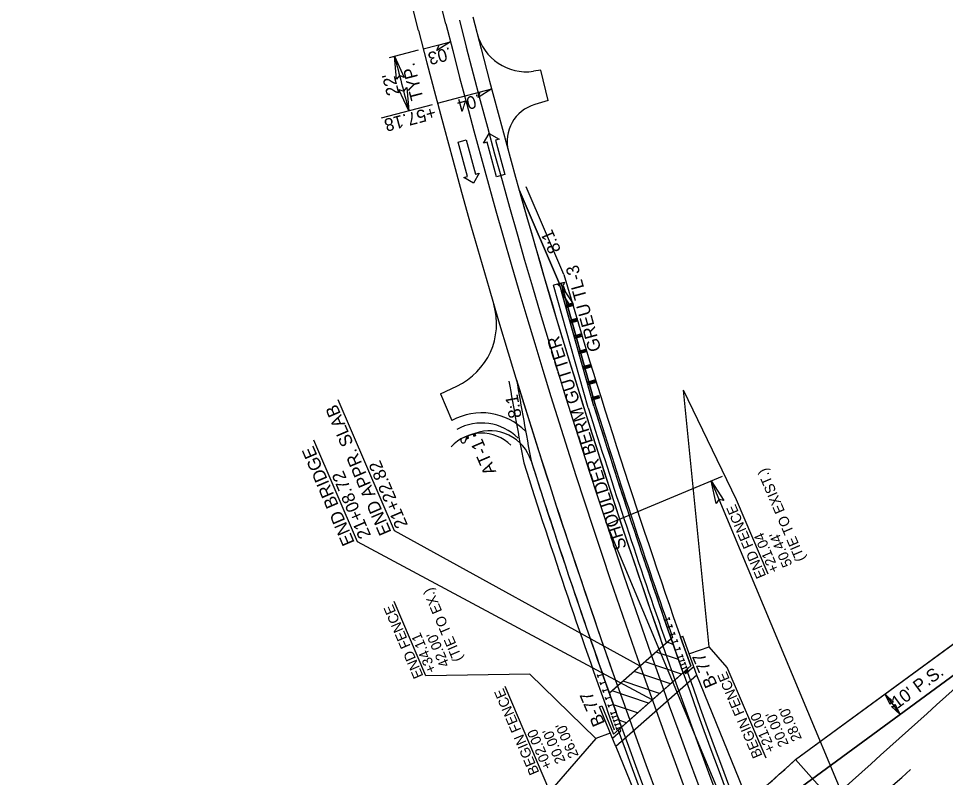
# Model space of a CAD drawing. Extents: x 1550950 to 1552827, y 809595 to 812050.
# Drawn here: x 1551529.1 to 1551892.9, y 810831.5 to 811129.6 of the extents above; entities that cross this region are included whole.
import ezdxf

# ---------------------------------------------------------------- set-up
doc = ezdxf.new("R2010")
doc.units = 0
for name, color, linetype in [('3D Cell Connection Region', 7, 'Continuous'), ('_CIVIL_CONSTRUCTION', 7, 'Continuous'), ('Catch Basin Box 24 Dia-Bottom CELL', 7, 'Continuous'), ('Construction Elements LEVEL', 7, 'Continuous'), ('Draft_Plan_Labels', 7, 'Continuous'), ('Drop Inlet Box Traffic Bearing 840 35-Bottom CELL', 7, 'Continuous'), ('Drop Inlet Box Type B 36 Dia-Bottom CELL', 7, 'Continuous'), ('Drop Inlet Grate 2 Narrow Slot and Flat Grates 840 29 36 Dia BD Apron-Top CELL', 7, 'Continuous'), ('Drop Inlet Grate 2 Narrow Slot and Flat Grates 840 29 36 Dia BD CELL', 7, 'Continuous'), ('Drop Inlet Grate 2 Narrow Slot and Flat Grates 840 29 36 Dia TB-Top CELL', 7, 'Continuous'), ('Drop Inlet Grate 2 Wide Slot and Flat Grates 840 20 36 Dia BD-Top CELL', 7, 'Continuous'), ('Drop Inlet Grate 3 Narrow Slot and Flat Grates 840 29 48 Dia-Top CELL', 7, 'Continuous'), ('Drop Inlet Grate 840 16 CELL', 7, 'Continuous'), ('E_NCDOT_Vertical_Profile_Ground_Line', 7, 'Continuous'), ('Junction Box with Slab Lid 840 31 66 Dia TB CELL', 7, 'Continuous'), ('P_HYD_Ditch_Flow_Arrow', 7, 'Continuous'), ('P_HYD_Drop_Inlet_Box_Traffic_Bearing_840_35-Bottom_CELL', 7, 'Continuous'), ('P_HYD_Pipe_RCP_15in_Class_III', 7, 'Continuous'), ('P_HYD_Pipe_RCP_Class_III', 7, 'Continuous'), ('P_NCDOT_SS_Cut_Line', 7, 'Continuous'), ('P_NCDOT_SS_Transition_Line', 7, 'Continuous'), ('RipRap Pad at Outlet CELL', 7, 'Continuous'), ('Typical Terminator CELL', 7, 'Continuous'), ('V Ditch Special Lateral Detail CELL', 7, 'Continuous'), ('V Ditch Special Lateral with PSRM Detail CELL', 7, 'Continuous')]:
    doc.layers.add(name, color=color, linetype=linetype)

msp = doc.modelspace()

# ---------------------------------------------------------------- linework, layer by layer
at = {"layer": '3D Cell Connection Region'}
for p, q in [((1551687.97, 811117.71), (1551698.63, 811120.44)), ((1551693.54, 811096.34), (1551714.81, 811101.97))]:
    msp.add_line(p, q, dxfattribs=at)
at = {"layer": '_CIVIL_CONSTRUCTION'}
for p, q in [((1551674.76, 811114.32), (1551686.03, 811117.22)), ((1551671.61, 811090.54), (1551691.61, 811095.83)), ((1551869.2, 810864.26), (1551875.12, 810856.2))]:
    msp.add_line(p, q, dxfattribs=at)
msp.add_arc((1554524.17, 811845.14), 2939.64, 194.38517, 194.81729, dxfattribs=at)
at = {"layer": 'Construction Elements LEVEL'}
for centre, radius, start, end in [((1554524.17, 811845.14), 2902, 197.40029, 199.12785), ((1551714.11, 810950.64), 17, 17.6574, 110.1482), ((1554524.17, 811845.14), 2932, 197.65742, 199.36731)]:
    msp.add_arc(centre, radius, start, end, dxfattribs=at)
at = {"layer": 'Draft_Plan_Labels'}
for points in [[(1551823.4, 810911.35), (1551810.91, 810940.51), (1551790.16, 810983.57)], [(1551773.14, 810875.24), (1551676.64, 810928.33), (1551654.58, 810979.87)], [(1551777.86, 810861.95), (1551662.11, 810924.02), (1551645.02, 810963.96)], [(1551729.74, 810872.08), (1551689.01, 810871.43), (1551676.53, 810900.59)], [(1551822.53, 810839.05), (1551807.3, 810874.62), (1551800.15, 810882.85)], [(1551755.67, 810846.81), (1551737.69, 810825.98), (1551720.06, 810867.17)]]:
    msp.add_lwpolyline(points, dxfattribs=at)
at = {"layer": 'Drop Inlet Box Traffic Bearing 840 35-Bottom CELL'}
for p, q in [((1551788.97, 810886.59), (1551789.91, 810886.93)), ((1551792.96, 810875.28), (1551788.97, 810886.59)), ((1551795.29, 810871.67), (1551789.91, 810886.93)), ((1551792.96, 810875.28), (1551762.64, 810848.53)), ((1551794.13, 810874.97), (1551790.94, 810872.16)), ((1551795.29, 810871.67), (1551763.55, 810843.66)), ((1551790.94, 810872.16), (1551790.58, 810873.18)), ((1551815.6, 810821.96), (1551795.29, 810871.67)), ((1551757.18, 810859.25), (1551758.11, 810859.63)), ((1551763.55, 810843.66), (1551757.18, 810859.25)), ((1551758.11, 810859.63), (1551762.64, 810848.53)), ((1551765.52, 810849.73), (1551762.25, 810846.84)), ((1551765.52, 810849.73), (1551765.15, 810850.74)), ((1551763.55, 810843.66), (1551783.9, 810793.84))]:
    msp.add_line(p, q, dxfattribs=at)
at = {"layer": 'Drop Inlet Box Type B 36 Dia-Bottom CELL'}
for p, q in [((1551741.39, 811025.43), (1551725.6, 811062.32)), ((1551834.13, 810838.5), (1551926.9, 810906.66))]:
    msp.add_line(p, q, dxfattribs=at)
for centre, radius, start, end in [((1554591.13, 811489.54), 2910.19, 189.93054, 190.56824), ((1554524.17, 811845.14), 2932, 197.65742, 199.53901), ((1544245.73, 819324.67), 11384.16, 311.678302, 311.803311)]:
    msp.add_arc(centre, radius, start, end, dxfattribs=at)
at = {"layer": 'Drop Inlet Grate 2 Narrow Slot and Flat Grates 840 29 36 Dia BD Apron-Top CELL'}
for radius, end in [(20, 119.2133), (16, 138.5611)]:
    msp.add_arc((1551710.94, 810950.7), radius, 44.6722, end, dxfattribs=at)
at = {"layer": 'Drop Inlet Grate 2 Narrow Slot and Flat Grates 840 29 36 Dia BD CELL'}
for p, q in [((1551759.95, 810930.85), (1551805.44, 810949.86)), ((1551800.94, 810947.98), (1551972.39, 810537.74)), ((1551759.95, 810930.85), (1551931.4, 810520.61))]:
    msp.add_line(p, q, dxfattribs=at)
msp.add_lwpolyline([(1551802.98, 810939.08), (1551800.94, 810947.98), (1551805.9, 810940.25), (1551803.98, 810940.69)], close=True, dxfattribs=at)
msp.add_arc((1554524.17, 811845.14), 2911.5, 194.24112, 221.47505, dxfattribs=at)
at = {"layer": 'Drop Inlet Grate 2 Narrow Slot and Flat Grates 840 29 36 Dia TB-Top CELL'}
for points in [[(1551677.44, 811105.72), (1551676.7, 811114.82), (1551680.5, 811106.45), (1551678.66, 811107.17)], [(1551681.49, 811102.46), (1551682.29, 811093.37), (1551678.43, 811101.71), (1551680.27, 811101)], [(1551871.24, 810860.18), (1551869.2, 810864.26), (1551872.52, 810861.09), (1551871.54, 810861.08)], [(1551873.08, 810860.29), (1551875.12, 810856.2), (1551871.79, 810859.38), (1551872.78, 810859.39)]]:
    msp.add_lwpolyline(points, close=True, dxfattribs=at)
at = {"layer": 'Drop Inlet Grate 2 Wide Slot and Flat Grates 840 20 36 Dia BD-Top CELL'}
for points in [[(1551792.6, 810880.18), (1551800.15, 810882.85), (1551790.16, 810983.57)], [(1551761.32, 810848.84), (1551755.67, 810846.81), (1551729.74, 810872.08)]]:
    msp.add_lwpolyline(points, dxfattribs=at)
at = {"layer": 'Drop Inlet Grate 3 Narrow Slot and Flat Grates 840 29 48 Dia-Top CELL'}
for p, q in [((1551928.66, 810895.54), (1551831.98, 810824.51)), ((1551785.82, 810886.42), (1551782.04, 810883.09)), ((1551764.25, 810867.39), (1551761.01, 810864.54))]:
    msp.add_line(p, q, dxfattribs=at)
for points in [[(1551725.6, 811062.32), (1551741.39, 811025.43), (1551742.03, 811025.61), (1551755.61, 810977.5)], [(1551834.13, 810838.5), (1551926.9, 810906.66), (1551933.24, 810899.72)]]:
    msp.add_lwpolyline(points, dxfattribs=at)
for centre, radius, start, end in [((1554538.86, 811849.77), 2921.39, 195.6373, 199.32316), ((1554591.13, 811489.54), 2910.19, 189.93054, 190.56824), ((1554546.06, 811852.37), 2951.05, 197.03857, 199.49788), ((1554552.91, 811854.67), 2931.6, 197.41026, 199.28573), ((1554553.02, 811854.85), 2962.43, 197.66709, 199.52935), ((1544245.73, 819324.67), 11384.16, 311.340061, 311.803311)]:
    msp.add_arc(centre, radius, start, end, dxfattribs=at)
at = {"layer": 'Drop Inlet Grate 840 16 CELL'}
for points in [[(1551698.63, 811120.44), (1551693.31, 811117.02), (1551694.15, 811119.3)], [(1551714.81, 811101.97), (1551709.52, 811098.5), (1551710.34, 811100.79)]]:
    msp.add_lwpolyline(points, close=True, dxfattribs=at)
at = {"layer": 'E_NCDOT_Vertical_Profile_Ground_Line'}
for p, q in [((1551740.58, 811025.19), (1551743.39, 811026.04)), ((1551741.74, 811024.32), (1551740.58, 811025.19)), ((1551742.34, 811022.36), (1551741.74, 811024.32)), ((1551742.14, 811022.79), (1551743.58, 811023.19)), ((1551743.58, 811023.19), (1551742.41, 811021.82)), ((1551743.39, 811026.04), (1551742.91, 811024.67)), ((1551742.91, 811024.67), (1551743.51, 811022.71)), ((1551743.85, 811022.23), (1551743.58, 811023.19)), ((1551742.14, 811022.79), (1551743.85, 811022.23)), ((1551754.97, 810977.31), (1551742.27, 811022.31)), ((1551742.92, 811022.53), (1551742.34, 811022.36)), ((1551742.41, 811021.82), (1551743.85, 811022.23)), ((1551745.21, 811017.52), (1551742.41, 811021.82)), ((1551743.51, 811022.71), (1551742.92, 811022.53)), ((1551743.85, 811022.23), (1551743.72, 811022.71)), ((1551746.69, 811017.94), (1551743.85, 811022.23)), ((1551743.74, 811017.11), (1551746.69, 811017.94)), ((1551745.48, 811016.56), (1551743.74, 811017.11)), ((1551744.01, 811016.14), (1551745.21, 811017.52)), ((1551744.01, 811016.14), (1551746.96, 811016.98)), ((1551745.48, 811016.56), (1551745.21, 811017.52)), ((1551745.21, 811017.52), (1551746.96, 811016.98)), ((1551746.69, 811017.94), (1551745.48, 811016.56)), ((1551746.96, 811016.98), (1551746.69, 811017.94)), ((1551745.45, 811011.04), (1551748.34, 811011.86)), ((1551747.17, 811010.49), (1551745.45, 811011.04)), ((1551745.72, 811010.08), (1551746.89, 811011.45)), ((1551745.72, 811010.08), (1551748.61, 811010.9)), ((1551747.17, 811010.49), (1551746.89, 811011.45)), ((1551746.89, 811011.45), (1551748.61, 811010.9)), ((1551748.34, 811011.86), (1551747.17, 811010.49)), ((1551748.61, 811010.9), (1551748.34, 811011.86)), ((1551747.16, 811004.98), (1551750.18, 811005.83)), ((1551748.94, 811004.44), (1551747.16, 811004.98)), ((1551747.43, 811004.02), (1551748.67, 811005.4)), ((1551747.43, 811004.02), (1551750.45, 811004.87)), ((1551748.94, 811004.44), (1551748.67, 811005.4)), ((1551748.67, 811005.4), (1551750.45, 811004.87)), ((1551750.18, 811005.83), (1551748.94, 811004.44)), ((1551750.45, 811004.87), (1551750.18, 811005.83)), ((1551748.87, 810998.91), (1551751.8, 810999.74)), ((1551749.15, 810997.95), (1551748.87, 810998.91)), ((1551750.61, 810998.36), (1551748.87, 810998.91)), ((1551749.15, 810997.95), (1551750.33, 810999.33)), ((1551749.15, 810997.95), (1551752.07, 810998.78)), ((1551750.61, 810998.36), (1551750.33, 810999.33)), ((1551750.33, 810999.33), (1551752.07, 810998.78)), ((1551751.8, 810999.74), (1551750.61, 810998.36)), ((1551752.07, 810998.78), (1551751.8, 810999.74)), ((1551750.59, 810992.85), (1551753.52, 810993.68)), ((1551752.32, 810992.3), (1551750.59, 810992.85)), ((1551750.86, 810991.89), (1551752.05, 810993.26)), ((1551750.86, 810991.89), (1551753.79, 810992.72)), ((1551752.32, 810992.3), (1551752.05, 810993.26)), ((1551752.05, 810993.26), (1551753.79, 810992.72)), ((1551753.52, 810993.68), (1551752.32, 810992.3)), ((1551753.79, 810992.72), (1551753.52, 810993.68)), ((1551752.3, 810986.79), (1551755.23, 810987.61)), ((1551754.04, 810986.24), (1551752.3, 810986.79)), ((1551752.57, 810985.82), (1551753.77, 810987.2)), ((1551752.57, 810985.82), (1551755.51, 810986.65)), ((1551754.04, 810986.24), (1551753.77, 810987.2)), ((1551753.77, 810987.2), (1551755.51, 810986.65)), ((1551755.23, 810987.61), (1551754.04, 810986.24)), ((1551755.51, 810986.65), (1551755.23, 810987.61)), ((1551754.01, 810980.72), (1551756.89, 810981.54)), ((1551754.01, 810980.72), (1551755.45, 810981.13)), ((1551754.28, 810979.76), (1551754.01, 810980.72)), ((1551755.72, 810980.17), (1551754.01, 810980.72)), ((1551755.45, 810981.13), (1551754.28, 810979.76)), ((1551754.28, 810979.76), (1551757.17, 810980.57)), ((1551755.72, 810980.17), (1551755.45, 810981.13)), ((1551755.45, 810981.13), (1551757.17, 810980.57)), ((1551756.89, 810981.54), (1551755.72, 810980.17)), ((1551757.17, 810980.57), (1551756.89, 810981.54)), ((1551704.92, 810965.38), (1551703.31, 810964.78)), ((1551704.6, 810963.57), (1551704.95, 810964.73)), ((1551705.39, 810965.55), (1551704.74, 810965.31)), ((1551704.74, 810965.31), (1551704.86, 810964.98)), ((1551704.74, 810965.31), (1551704.86, 810964.98)), ((1551704.74, 810965.31), (1551705.02, 810964.55)), ((1551704.74, 810965.31), (1551705.67, 810964.79)), ((1551704.86, 810965.35), (1551704.99, 810965.4)), ((1551704.86, 810965.35), (1551704.99, 810965.4)), ((1551708.25, 810966.6), (1551704.92, 810965.38)), ((1551705.39, 810965.55), (1551705.02, 810964.55)), ((1551705.02, 810964.55), (1551705.67, 810964.79)), ((1551705.67, 810964.79), (1551705.39, 810965.55)), ((1551708.25, 810966.6), (1551707.59, 810966.36)), ((1551707.59, 810966.36), (1551707.87, 810965.6)), ((1551707.59, 810966.36), (1551708.53, 810965.84)), ((1551708.25, 810966.6), (1551707.87, 810965.6)), ((1551707.87, 810965.6), (1551708.53, 810965.84)), ((1551708.53, 810965.84), (1551708.25, 810966.6))]:
    msp.add_line(p, q, dxfattribs=at)
msp.add_ellipse((1551703.65, 810963.85), major_axis=(0.342, -0.932), ratio=0.995379, start_param=3.141593, end_param=7.214552, dxfattribs=at)
at = {"layer": 'Junction Box with Slab Lid 840 31 66 Dia TB CELL'}
msp.add_line((1551743.11, 811029.04), (1551728.35, 811063.5), dxfattribs=at)
for centre, radius, start, end in [((1554524.17, 811845.14), 2898.33, 196.35432, 199.55017), ((1554591.13, 811489.54), 2913.19, 189.93054, 190.57189), ((1554524.17, 811845.14), 2935, 197.65379, 199.81432)]:
    msp.add_arc(centre, radius, start, end, dxfattribs=at)
at = {"layer": 'P_HYD_Ditch_Flow_Arrow'}
msp.add_line((1551834.13, 810838.5), (1551884.12, 810782.59), dxfattribs=at)
for centre, radius, start, end in [((1554524.17, 811845.14), 2917, 194.24112, 221.47505), ((1544245.73, 819324.67), 11417.16, 311.218611, 311.958611)]:
    msp.add_arc(centre, radius, start, end, dxfattribs=at)
at = {"layer": 'P_HYD_Pipe_RCP_15in_Class_III'}
msp.add_line((1551696.81, 811127.55), (1551623.96, 811414.59), dxfattribs=at)
at = {"layer": 'P_HYD_Pipe_RCP_Class_III'}
for p, q in [((1551701.61, 811081.06), (1551704.8, 811081.92)), ((1551704.8, 811081.92), (1551708.46, 811068.41)), ((1551711.64, 811080.58), (1551713.81, 811084.43)), ((1551713.81, 811084.43), (1551717.72, 811082.23)), ((1551717.72, 811082.23), (1551716.27, 811081.83)), ((1551716.27, 811081.83), (1551719.93, 811068.32)), ((1551705.27, 811067.55), (1551701.61, 811081.06)), ((1551713.09, 811080.97), (1551711.64, 811080.58)), ((1551716.74, 811067.46), (1551713.09, 811080.97)), ((1551703.82, 811067.16), (1551705.27, 811067.55)), ((1551707.74, 811064.95), (1551703.82, 811067.16)), ((1551709.9, 811068.8), (1551707.74, 811064.95)), ((1551708.46, 811068.41), (1551709.9, 811068.8)), ((1551719.93, 811068.32), (1551716.74, 811067.46))]:
    msp.add_line(p, q, dxfattribs=at)
at = {"layer": 'P_NCDOT_SS_Cut_Line'}
for p, q in [((1551786.04, 810883.77), (1551783.7, 810884.56)), ((1551788.15, 810877.79), (1551779.37, 810880.74)), ((1551789.37, 810872.11), (1551775.04, 810876.91)), ((1551785.04, 810868.29), (1551770.71, 810873.09)), ((1551780.71, 810864.46), (1551766.38, 810869.27)), ((1551776.38, 810860.64), (1551762.05, 810865.45)), ((1551772.05, 810856.82), (1551762.64, 810859.98)), ((1551767.72, 810853), (1551764.78, 810853.99))]:
    msp.add_line(p, q, dxfattribs=at)
at = {"layer": 'P_NCDOT_SS_Transition_Line'}
for p, q in [((1551789.97, 810872.64), (1551782.39, 810894.22)), ((1551782.72, 810893.28), (1551784.61, 810893.94)), ((1551784.8, 810893.4), (1551784.42, 810894.48)), ((1551783.76, 810890.33), (1551785.65, 810890.99)), ((1551785.84, 810890.45), (1551785.46, 810891.53)), ((1551786.87, 810887.51), (1551786.49, 810888.59)), ((1551784.79, 810887.38), (1551786.68, 810888.05)), ((1551785.83, 810884.43), (1551787.72, 810885.1)), ((1551787.91, 810884.56), (1551787.53, 810885.64)), ((1551786.87, 810881.49), (1551788.75, 810882.15)), ((1551788.94, 810881.61), (1551788.56, 810882.69)), ((1551787.9, 810878.54), (1551789.79, 810879.2)), ((1551788.42, 810877.06), (1551790.31, 810877.73)), ((1551789.98, 810878.66), (1551789.6, 810879.74)), ((1551790.5, 810877.19), (1551790.12, 810878.27)), ((1551788.94, 810875.59), (1551790.82, 810876.25)), ((1551789.45, 810874.11), (1551791.34, 810874.78)), ((1551791.01, 810875.71), (1551790.63, 810876.79)), ((1551791.53, 810874.24), (1551791.15, 810875.32)), ((1551792.05, 810872.76), (1551791.67, 810873.84)), ((1551756.73, 810870.67), (1551756.35, 810871.75)), ((1551758.42, 810871.88), (1551756.54, 810871.21)), ((1551765.76, 810851.27), (1551758.09, 810872.82)), ((1551789.97, 810872.64), (1551791.86, 810873.3)), ((1551757.78, 810867.73), (1551757.39, 810868.81)), ((1551759.47, 810868.94), (1551757.59, 810868.27)), ((1551758.83, 810864.78), (1551758.44, 810865.86)), ((1551760.52, 810865.99), (1551758.63, 810865.32)), ((1551759.87, 810861.84), (1551759.49, 810862.92)), ((1551761.57, 810863.05), (1551759.68, 810862.38)), ((1551760.92, 810858.9), (1551760.54, 810859.97)), ((1551762.61, 810860.11), (1551760.73, 810859.43)), ((1551761.97, 810855.95), (1551761.59, 810857.03)), ((1551763.66, 810857.16), (1551761.78, 810856.49)), ((1551762.49, 810854.48), (1551762.11, 810855.56)), ((1551764.19, 810855.69), (1551762.3, 810855.02)), ((1551763.02, 810853.01), (1551762.63, 810854.09)), ((1551764.71, 810854.22), (1551762.83, 810853.55)), ((1551763.54, 810851.53), (1551763.16, 810852.61)), ((1551765.23, 810852.74), (1551763.35, 810852.07)), ((1551764.07, 810850.06), (1551763.68, 810851.14)), ((1551765.76, 810851.27), (1551763.87, 810850.6))]:
    msp.add_line(p, q, dxfattribs=at)
at = {"layer": 'RipRap Pad at Outlet CELL'}
for p, q in [((1551742.03, 811025.61), (1551739.14, 811024.8)), ((1551752.73, 810976.65), (1551739.14, 811024.8)), ((1551754.97, 810977.31), (1551741.39, 811025.43)), ((1551755.61, 810977.5), (1551742.03, 811025.61)), ((1551783.39, 810884.28), (1551785.82, 810886.42))]:
    msp.add_line(p, q, dxfattribs=at)
for radius, start, end in [(2904.33, 197.3996, 199.31958), (2902, 197.40029, 199.30086), (2901.33, 197.40047, 199.29551)]:
    msp.add_arc((1554524.17, 811845.14), radius, start, end, dxfattribs=at)
at = {"layer": 'Typical Terminator CELL'}
msp.add_line((1551791.29, 810873.8), (1551764.45, 810850.12), dxfattribs=at)
for radius, start, end in [(2900.37, 199.56661, 204.64059), (2902, 199.57948, 204.65027), (2933.62, 199.82689, 204.83638), (2932, 199.81432, 204.82692)]:
    msp.add_arc((1554524.17, 811845.14), radius, start, end, dxfattribs=at)
at = {"layer": 'V Ditch Special Lateral Detail CELL'}
msp.add_line((1551785.28, 810885.95), (1551761.01, 810864.54), dxfattribs=at)
for radius, start, end in [(2902, 199.30086, 199.57948), (2932, 199.53901, 199.81432)]:
    msp.add_arc((1554524.17, 811845.14), radius, start, end, dxfattribs=at)
at = {"layer": 'V Ditch Special Lateral with PSRM Detail CELL'}
for p, q in [((1551686.15, 811124.84), (1551670.53, 811186.38)), ((1551737.03, 811097.33), (1551731.75, 811095.81)), ((1551694.7, 810982.23), (1551701.13, 810985.22)), ((1551694.7, 810982.23), (1551699.23, 810971.64)), ((1551831.98, 810824.51), (1551928.66, 810895.54))]:
    msp.add_line(p, q, dxfattribs=at)
msp.add_lwpolyline([(1551737.03, 811097.33), (1551734.15, 811109.24), (1551731.23, 811108.84)], dxfattribs=at)
for centre, radius, start, end in [((1554524.17, 811845.14), 2906, 194.24112, 210.67194), ((1554524.17, 811845.14), 2928, 194.24112, 210.67194), ((1551728.52, 811128.66), 20, 194.3747, 277.7813), ((1551735.88, 811081.39), 15, 106, 195.3183), ((1551689.73, 811009.7), 27, 294.9692, 16.4227), ((1551710.94, 810950.7), 24, 44.141, 119.2133), ((1544245.73, 819324.67), 11459.16, 307.933611, 313.133611), ((1544245.73, 819324.67), 11405.16, 310.795027, 312.379469)]:
    msp.add_arc(centre, radius, start, end, dxfattribs=at)

# ---------------------------------------------------------------- texts
at = {"layer": 'Catch Basin Box 24 Dia-Bottom CELL'}
for s, rotation, p in [('.03', 194.3852, (1551698.4, 811118.4)), ('.04', 194.8173, (1551709.8, 811099.96))]:
    msp.add_text(s, height=5, rotation=rotation, dxfattribs=at).set_placement(p)
at = {"layer": 'Draft_Plan_Labels'}
for s, height, rotation, p in [('8:1', 5, 113.2095, (1551742.1, 811038.58)), ('GREU TL-3', 5, 105.3642, (1551757.85, 810999.48)), ('SHOULDER BERM GUTTER', 5, 107.7946, (1551767.92, 810921.81)), ('8:1', 5, 100.1615, (1551726.6, 810973.04)), ('END APPR. SLAB', 5, 113.1736, (1551675.57, 810927.87)), ('END BRIDGE', 5, 113.1736, (1551661.12, 810923.8)), ('AT-1', 5, 113.1736, (1551716.68, 810951.56)), ('21+22.82', 5, 113.1736, (1551682.01, 810930.62)), ('21+08.72', 5, 113.1736, (1551667.55, 810926.55)), ('(TIE TO EXIST.)', 4, 113.1736, (1551838.05, 810917.27)), ('END FENCE', 4, 113.1736, (1551822.61, 810910.66)), ('+21.04', 4, 113.1736, (1551827.75, 810912.87)), ("50.44'", 4, 113.1736, (1551832.9, 810915.07)), ('(TIE TO EX.)', 4, 113.1736, (1551703.53, 810877.96)), ('END FENCE', 4, 113.1736, (1551688.08, 810871.35)), ('+34.11', 4, 113.1736, (1551693.23, 810873.55)), ("42.00'", 4, 113.1736, (1551698.38, 810875.75)), ('B-77', 5, 113.1736, (1551803.5, 810867.97)), ("10' P.S.", 5, 36.5182, (1551874.04, 810858.28)), ('BEGIN FENCE', 4, 113.1736, (1551821.2, 810840.08)), ('BEGIN FENCE', 4, 113.1736, (1551733.59, 810833.49)), ('B-77', 5, 113.1736, (1551759.37, 810852.81)), ('+21.00', 4, 113.1736, (1551826.35, 810842.29)), ("20.00'", 4, 113.1736, (1551831.49, 810844.49)), ("28.00'", 4, 113.1736, (1551836.64, 810846.7)), ("26.00'", 4, 113.1736, (1551749.03, 810840.1)), ('+02.00', 4, 113.1736, (1551738.74, 810835.69)), ("20.00'", 4, 113.1736, (1551743.88, 810837.9))]:
    msp.add_text(s, height=height, rotation=rotation, dxfattribs=at).set_placement(p)
at = {"layer": 'P_HYD_Drop_Inlet_Box_Traffic_Bearing_840_35-Bottom_CELL'}
for s, rotation, p in [('TYP.', 104.6111, (1551688.08, 811098.21)), ("22'", 104.6007, (1551678.67, 811100.03)), ('+57.18', 194.8173, (1551692.17, 811095.17))]:
    msp.add_text(s, height=5, rotation=rotation, dxfattribs=at).set_placement(p)

doc.saveas('drawing.dxf')
